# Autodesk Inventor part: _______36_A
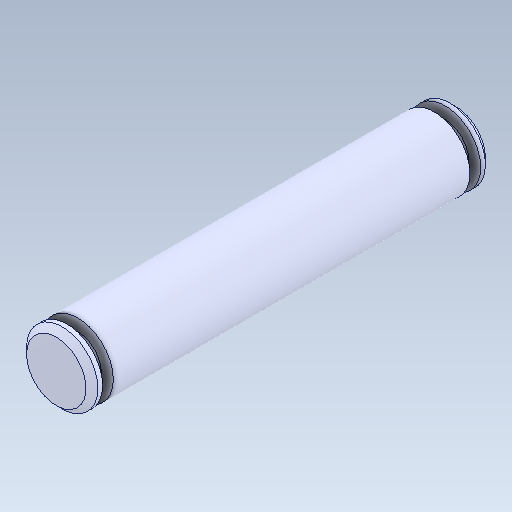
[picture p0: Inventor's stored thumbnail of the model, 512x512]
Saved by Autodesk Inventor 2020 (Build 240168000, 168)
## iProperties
Created: 2017-09
Part Number: _______36_A
Material: Générique
Document SubType Name: Modeling
Designer: bruno
Density: 1 g/cm^3
Appearance: Par défaut
Author: bruno
Sending System: SolidWorks 2016
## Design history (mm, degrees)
feature "Importée1"
node "Solide1"
